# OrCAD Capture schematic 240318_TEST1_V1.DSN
size A4; title: VOLTAGE CONTROLLED OSCILLATOR; rev: 1.0; note: 炔盲戎. 2024.03.18
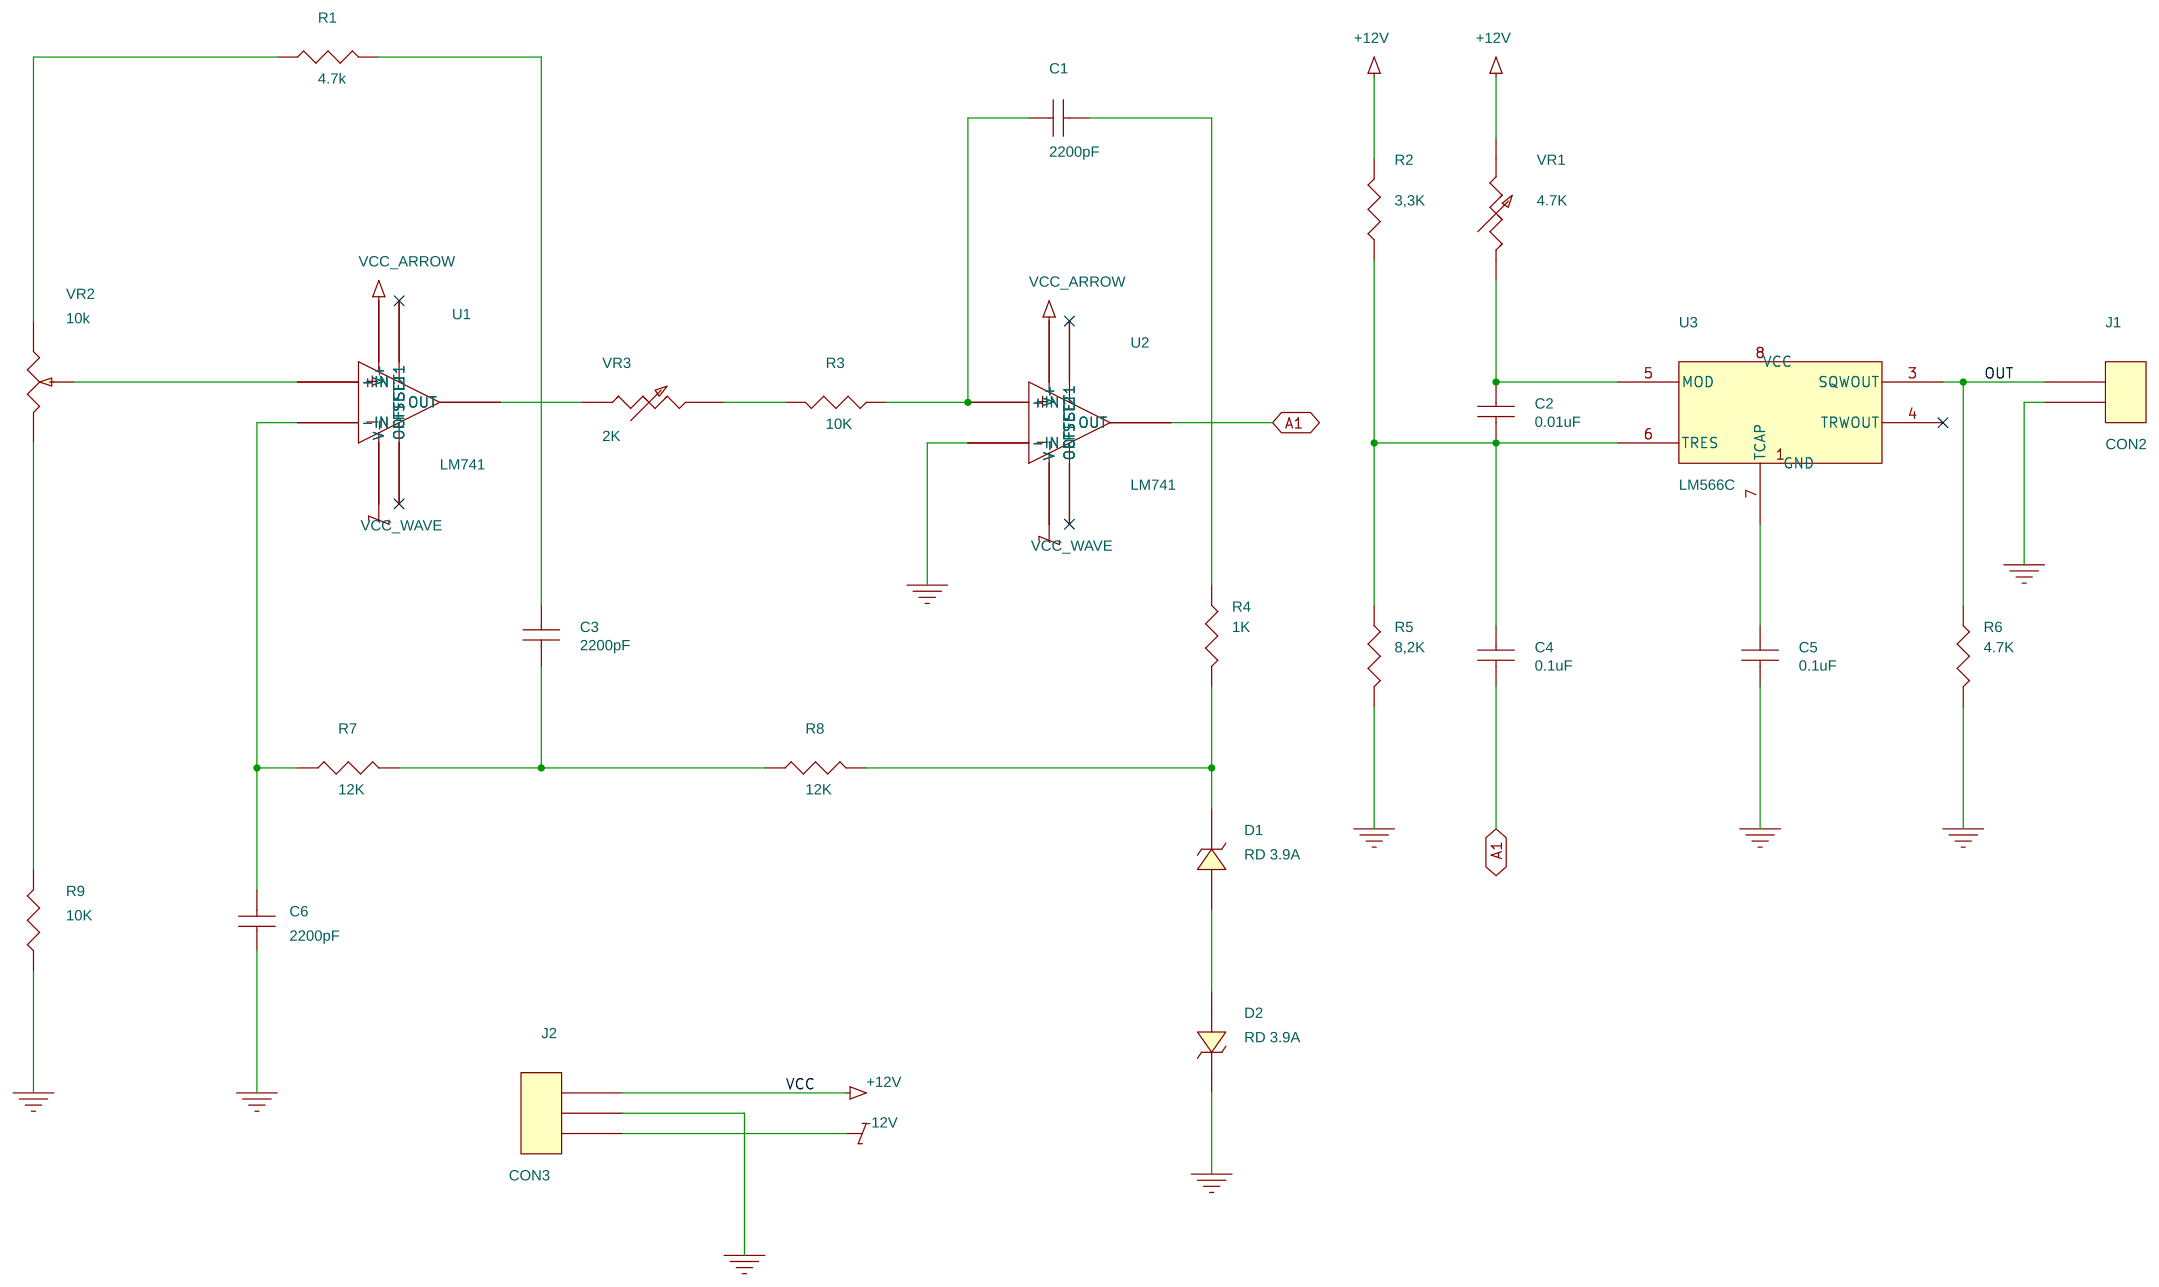
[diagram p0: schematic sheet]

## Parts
C1  2200pF  [CAPCK05]
C2  0.01uF  [CAPCK05]
C3  2200pF  [CAPCK05]
C4  0.1uF  [CAPCK05]
C5  0.1uF  [CAPCK05]
C6  2200pF  [CAPCK05]
D1  RD 3.9A  [DO41]
D2  RD 3.9A  [DO41]
J1  CON2  [JUMPER2]
J2  CON3  [JUMPER3]
R1  4.7k  [RES400]
R2  3,3K  [RES400]
R3  10K  [RES400]
R4  1K  [RES400]
R5  8,2K  [RES400]
R6  4.7K  [RES400]
R7  12K  [RES400]
R8  12K  [RES400]
R9  10K  [RES400]
U1  LM741  [DIP8_3]
U2  LM741  [DIP8_3]
U3  LM566C  [DIP8_3]
VR1  4.7K  [RESADJ]
VR2  10k  [RESADJ]
VR3  2K  [RESADJ]

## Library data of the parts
C1-C6 = CAP_NP
D1 D2 = DIODE_ZENER
J1 = CON2
J2 = CON3
R1-R9 = R
U1 U2 = LM741_0: NC: 8
U3 = LM566C_3: NC: 2
VR1 VR3 = RESISTOR_VAR_2: NC: 3
VR2 = RESISTOR_VAR

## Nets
+12V: J2.1 R2.2 U1.7(V+) U2.7(V+) U3.8(VCC) VR1.2
-12V: J2.3 U1.4(V-) U2.4(V-)
GND: C5.2 C6.1 D2.1(CATHODE) J1.2 J2.2 R5.2 R6.2 R9.1 U2.2(-IN) U3.1(GND)
A1: C4.2 U2.6(OUT)
OUT: J1.1 R6.1 U3.3(SQWOUT)
N01144: R1.1 VR2.1(A)
N01158: U1.3(+IN) VR2.2(WIPER)
N01162: U1.6(OUT) VR3.1
N01166: C3.1 R1.2
N01173: C6.2 R7.1 U1.2(-IN)
N01186: R9.2 VR2.3(B)
N01206: C3.2 R7.2 R8.1
N01220: R3.2 VR3.2
N01242: C1.1 R3.1 U2.3(+IN)
N01254: C1.2 R4.1
N01261: D1.1(CATHODE) R4.2 R8.2
N01265: D1.2(ANODE) D2.2(ANODE)
N01354: C2.2 C4.1 R2.1 R5.1 U3.6(TRES)
N01358: C2.1 U3.5(MOD) VR1.1
N01436: C5.1 U3.7(TCAP)

Not connected (* = marked no-connect by the designer): U1 1(OFFSET1)* 5(OFFSET2)*; U2 1(OFFSET1)* 5(OFFSET2)*; U3 4(TRWOUT)*
